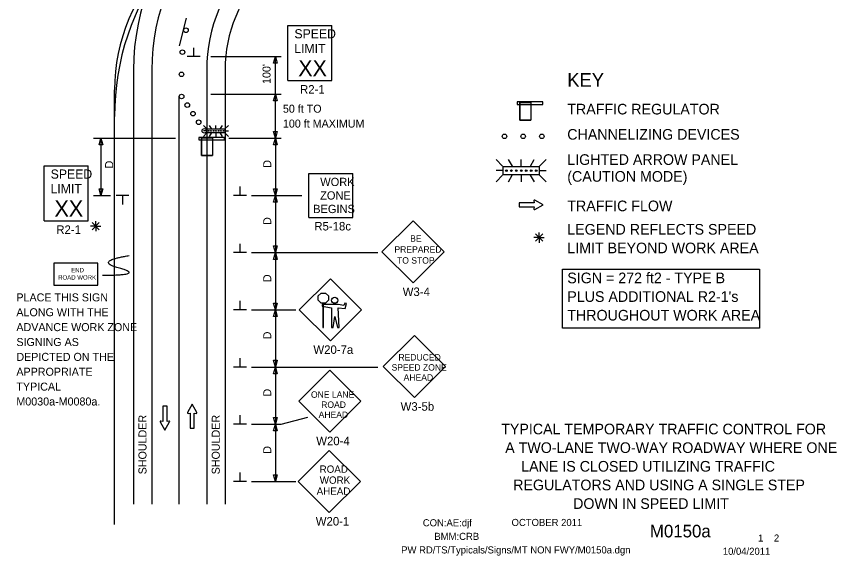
# Model space of a CAD drawing. Extents: x 16735 to 18481, y 5932 to 6923.
# Drawn here: x 16735 to 17452, y 5932 to 6404 of the extents above; entities that cross this region are included whole.
import ezdxf

# ---------------------------------------------------------------- set-up
doc = ezdxf.new("R2010")
doc.units = 0
for name, color, linetype in [('ALI_LEGAL_EX', 7, 'Continuous'), ('BORDER_SIGNAL_WO', 7, 'Continuous'), ('MT_SCRATCH_LEVEL_E', 7, 'Continuous'), ('PAVT_EDGE_EX', 7, 'Continuous'), ('TRAFFIC_SIGNS_PR', 7, 'Continuous'), ('TYPICAL_TEXT_DIMEN_EX', 7, 'Continuous'), ('TYPICAL_TEXT_DIMEN_PR', 7, 'Continuous')]:
    doc.layers.add(name, color=color, linetype=linetype)

msp = doc.modelspace()

# ---------------------------------------------------------------- linework, layer by layer
at = {"layer": 'ALI_LEGAL_EX'}
msp.add_line((16821.31, 5959.79), (16821.31, 6316.41), dxfattribs=at)
msp.add_arc((17042.09, 6317.17), 220.78, 142.68987, 180.19827, dxfattribs=at)
at = {"layer": 'MT_SCRATCH_LEVEL_E'}
for p, q in [((17188.17, 6240.97), (17174.91, 6240.97)), ((17174.91, 6240.97), (17174.91, 6237.23)), ((17188.17, 6240.97), (17174.91, 6240.97)), ((17174.91, 6240.97), (17174.91, 6237.23)), ((17174.91, 6237.23), (17188.17, 6237.23)), ((17174.91, 6237.23), (17188.17, 6237.23)), ((17187.85, 6242.75), (17188.17, 6240.97)), ((17187.85, 6242.75), (17188.17, 6240.97)), ((17188.17, 6237.23), (17187.85, 6235.45)), ((17188.17, 6237.23), (17187.85, 6235.45)), ((17195.78, 6239.12), (17188.54, 6243.23)), ((17195.78, 6239.12), (17188.54, 6243.23)), ((17188.54, 6234.97), (17195.78, 6239.12)), ((17188.54, 6234.97), (17195.78, 6239.12)), ((16867.14, 6063.03), (16863.4, 6063.03)), ((16863.4, 6063.03), (16863.4, 6049.78)), ((16867.14, 6063.03), (16863.4, 6063.03)), ((16863.4, 6063.03), (16863.4, 6049.78)), ((16867.14, 6049.78), (16867.14, 6063.03)), ((16867.14, 6049.78), (16867.14, 6063.03)), ((16889.11, 6064.72), (16885, 6057.48)), ((16889.11, 6064.72), (16885, 6057.48)), ((16893.26, 6057.48), (16889.11, 6064.72)), ((16893.26, 6057.48), (16889.11, 6064.72)), ((16885.48, 6056.8), (16887.26, 6057.11)), ((16885.48, 6056.8), (16887.26, 6057.11)), ((16887.26, 6057.11), (16887.26, 6043.86)), ((16887.26, 6057.11), (16887.26, 6043.86)), ((16891, 6043.86), (16891, 6057.11)), ((16891, 6057.11), (16892.78, 6056.8)), ((16891, 6043.86), (16891, 6057.11)), ((16891, 6057.11), (16892.78, 6056.8)), ((16861.15, 6049.41), (16865.29, 6042.17)), ((16861.15, 6049.41), (16865.29, 6042.17)), ((16863.4, 6049.78), (16861.62, 6050.09)), ((16863.4, 6049.78), (16861.62, 6050.09)), ((16865.29, 6042.17), (16869.4, 6049.41)), ((16865.29, 6042.17), (16869.4, 6049.41)), ((16868.92, 6050.09), (16867.14, 6049.78)), ((16868.92, 6050.09), (16867.14, 6049.78)), ((16887.26, 6043.86), (16891, 6043.86)), ((16887.26, 6043.86), (16891, 6043.86))]:
    msp.add_line(p, q, dxfattribs=at)
for centre, start, end in [((17188.31, 6242.82), 60.42484, 189.96381), ((17188.31, 6242.82), 60.42484, 189.96381), ((17188.31, 6235.38), 170.03619, 299.77312), ((17188.31, 6235.38), 170.03619, 299.77312), ((16885.41, 6057.26), 150.42484, 279.96381), ((16885.41, 6057.26), 150.42484, 279.96381), ((16892.85, 6057.26), 260.03619, 29.77312), ((16892.85, 6057.26), 260.03619, 29.77312), ((16861.55, 6049.63), 80.03619, 209.77312), ((16861.55, 6049.63), 80.03619, 209.77312), ((16869, 6049.63), 330.42484, 99.96381), ((16869, 6049.63), 330.42484, 99.96381)]:
    msp.add_arc(centre, 0.463, start, end, dxfattribs=at)
at = {"layer": 'PAVT_EDGE_EX'}
for p, q in [((16837.83, 6357.23), (16837.83, 5977.53)), ((16853.83, 6357.23), (16853.83, 5977.53)), ((16901.83, 6357.23), (16901.83, 5977.53)), ((16917.83, 6357.23), (16917.83, 5977.53)), ((16821.31, 5959.79), (16821.31, 6339.5)), ((16877.83, 5977.53), (16877.83, 6334.14))]:
    msp.add_line(p, q, dxfattribs=at)
for points in [[(16878.08, 6378.11), (16884.28, 6402.33)], [(16877.83, 6277.53), (16877.83, 6302.53)], [(16877.83, 6277.53), (16877.83, 6302.53)], [(16877.83, 6177.53), (16877.83, 6202.53)], [(16877.83, 6177.53), (16877.83, 6202.53)], [(16877.83, 6077.53), (16877.83, 6102.53)], [(16877.83, 6077.53), (16877.83, 6102.53)], [(16877.83, 5977.53), (16877.83, 6002.53)], [(16877.83, 5977.53), (16877.83, 6002.53)]]:
    msp.add_lwpolyline(points, dxfattribs=at)
for centre, radius, start, end in [((17037.83, 6357.23), 200, 134.42576, 179.99991), ((17037.83, 6357.23), 184, 134.42582, 180.00009), ((16981.31, 6339.5), 160, 134.35623, 180.00012), ((17037.83, 6357.23), 136, 134.35623, 180.00013), ((17037.83, 6357.23), 120, 134.35623, 180.00014)]:
    msp.add_arc(centre, radius, start, end, dxfattribs=at)
at = {"layer": 'TRAFFIC_SIGNS_PR'}
for p, q in [((16972.73, 6395.76), (17011.13, 6395.76)), ((16972.73, 6347.76), (16972.73, 6395.76)), ((17011.13, 6347.76), (17011.13, 6395.76)), ((16972.73, 6347.76), (17011.13, 6347.76)), ((17175.6, 6328.65), (17175.6, 6313.05)), ((17185.19, 6328.65), (17185.19, 6313.05)), ((17175.6, 6313.05), (17185.19, 6313.05)), ((16898.92, 6308.57), (16901.74, 6305.75)), ((16901.74, 6303.72), (16898.92, 6303.72)), ((16898.92, 6298.87), (16901.74, 6301.69)), ((16903.38, 6303.72), (16903.38, 6303.72)), ((16904.36, 6298.86), (16905.99, 6301.69)), ((16906.01, 6305.75), (16904.39, 6308.57)), ((16905.56, 6303.72), (16905.56, 6303.72)), ((16907.73, 6303.72), (16907.73, 6303.72)), ((16909.83, 6305.75), (16909.83, 6308.57)), ((16909.83, 6301.69), (16909.83, 6298.86)), ((16909.9, 6303.72), (16909.9, 6303.72)), ((16912.08, 6303.72), (16912.08, 6303.72)), ((16913.96, 6305.75), (16915.59, 6308.57)), ((16915.62, 6298.86), (16913.99, 6301.69)), ((16914.25, 6303.72), (16914.25, 6303.72)), ((16916.42, 6303.72), (16916.42, 6303.72)), ((16917.91, 6305.75), (16920.74, 6308.57)), ((16917.91, 6303.72), (16920.74, 6303.72)), ((16917.91, 6301.69), (16920.74, 6298.86)), ((16897.31, 6297.69), (16897.31, 6282.08)), ((16906.89, 6297.69), (16906.89, 6282.08)), ((16897.31, 6282.08), (16906.89, 6282.08)), ((16759.69, 6273.11), (16798.09, 6273.11)), ((16759.69, 6225.11), (16759.69, 6273.11)), ((16798.09, 6225.11), (16798.09, 6273.11)), ((17154.83, 6278.65), (17160.47, 6273.01)), ((17169.01, 6273.01), (17165.75, 6278.65)), ((17176.64, 6273.01), (17176.64, 6278.65)), ((17184.91, 6273.01), (17188.16, 6278.65)), ((17192.81, 6273.01), (17198.45, 6278.65)), ((16991.07, 6228.14), (16991.07, 6266.53)), ((16991.07, 6266.53), (17029.47, 6266.53)), ((17029.47, 6228.14), (17029.47, 6266.53)), ((17160.47, 6268.95), (17154.83, 6268.95)), ((17163.74, 6268.95), (17163.74, 6268.95)), ((17168.09, 6268.95), (17168.09, 6268.95)), ((17172.44, 6268.95), (17172.44, 6268.95)), ((17176.79, 6268.95), (17176.79, 6268.95)), ((17181.13, 6268.95), (17181.13, 6268.95)), ((17185.48, 6268.95), (17185.48, 6268.95)), ((17189.83, 6268.95), (17189.83, 6268.95)), ((17192.81, 6268.95), (17198.45, 6268.95)), ((17154.83, 6259.25), (17160.47, 6264.88)), ((17165.7, 6259.24), (17168.95, 6264.88)), ((17176.64, 6264.88), (17176.64, 6259.24)), ((17188.21, 6259.24), (17184.96, 6264.88)), ((17192.81, 6264.88), (17198.45, 6259.24)), ((16759.69, 6225.11), (16798.09, 6225.11)), ((16991.07, 6228.14), (17029.47, 6228.14)), ((17082.14, 6225.12), (17054.99, 6197.96)), ((17109.3, 6197.96), (17082.14, 6225.12)), ((17054.99, 6197.96), (17082.14, 6170.81)), ((17082.14, 6170.81), (17109.3, 6197.96)), ((17009.93, 6174.53), (16982.78, 6147.38)), ((17037.08, 6147.38), (17009.93, 6174.53)), ((16982.78, 6147.38), (17009.93, 6120.22)), ((17009.93, 6120.22), (17037.08, 6147.38)), ((17083.33, 6124.84), (17056.18, 6097.68)), ((17110.49, 6097.68), (17083.33, 6124.84)), ((17009.37, 6094.69), (16982.22, 6067.54)), ((17036.52, 6067.54), (17009.37, 6094.69)), ((17056.18, 6097.68), (17083.33, 6070.53)), ((17083.33, 6070.53), (17110.49, 6097.68)), ((16982.22, 6067.54), (17009.37, 6040.39)), ((17009.37, 6040.39), (17036.52, 6067.54)), ((17008.97, 6024.47), (16981.82, 5997.32)), ((17036.12, 5997.32), (17008.97, 6024.47)), ((16981.82, 5997.32), (17008.97, 5970.17)), ((17008.97, 5970.17), (17036.12, 5997.32))]:
    msp.add_line(p, q, dxfattribs=at)
for points in [[(17195.6, 6328.98), (17173.22, 6328.98), (17173.22, 6326.88), (17195.6, 6326.88)], [(17175.6, 6328.65), (17185.19, 6328.65), (17185.19, 6313.05), (17175.6, 6313.05)], [(16917.68, 6301.92), (16901.98, 6301.92), (16901.98, 6305.52), (16917.68, 6305.52)], [(16917.3, 6298.02), (16894.92, 6298.02), (16894.92, 6295.92), (16917.3, 6295.92)], [(16897.31, 6297.69), (16906.89, 6297.69), (16906.89, 6282.08), (16897.31, 6282.08)], [(17192.35, 6265.35), (17160.93, 6265.35), (17160.93, 6272.55), (17192.35, 6272.55)], [(16768.35, 6168.96), (16806.75, 6168.96), (16806.75, 6188.16), (16768.35, 6188.16)], [(17001.89, 6162.01), (17005.57, 6162.01), (17008.17, 6159.41), (17008.17, 6155.74), (17005.57, 6153.14), (17001.89, 6153.14), (16999.3, 6155.74), (16999.3, 6159.41)], [(17016.61, 6152.1), (17002.79, 6152.1), (17002.79, 6150.6), (17010.76, 6149.14), (17010.76, 6131.74), (17012.26, 6131.74), (17013.76, 6141.34), (17016.16, 6131.74), (17017.66, 6131.74), (17016.76, 6149.14), (17022.76, 6148.54), (17023.96, 6152.74), (17022.5, 6153.11), (17021.6, 6151.01)], [(17003.43, 6153.14), (17003.43, 6131.76), (17004.03, 6131.76), (17004.03, 6153.14)]]:
    msp.add_lwpolyline(points, close=True, dxfattribs=at)
for centre, radius in [((16883.63, 6391.67), 2), ((16880.58, 6372.54), 2), ((16879.83, 6353.18), 2), ((16879.87, 6333.79), 2), ((16884.84, 6326.28), 2), ((16889.81, 6318.78), 2), ((16894.78, 6311.27), 2), ((16899.75, 6303.77), 2), ((16903.4, 6303.72), 0.379), ((16905.55, 6303.72), 0.379), ((16907.73, 6303.72), 0.379), ((16909.9, 6303.72), 0.379), ((16912.08, 6303.72), 0.379), ((16914.25, 6303.72), 0.379), ((16916.42, 6303.72), 0.379), ((17162.15, 6298.98), 2), ((17178.45, 6298.98), 2), ((17194.75, 6298.98), 2), ((17163.78, 6268.95), 0.758), ((17168.09, 6268.95), 0.758), ((17172.44, 6268.95), 0.758), ((17176.79, 6268.95), 0.758), ((17181.13, 6268.95), 0.758), ((17185.48, 6268.95), 0.758), ((17189.83, 6268.95), 0.758), ((17013.74, 6155.71), 2.7)]:
    msp.add_circle(centre, radius, dxfattribs=at)
msp.add_open_spline([(16810.87, 6177.57), (16848.26, 6177.57), (16802.77, 6189.69), (16833.92, 6194.74)], degree=2, dxfattribs=at)
at = {"layer": 'TYPICAL_TEXT_DIMEN_EX'}
msp.add_lwpolyline([(17212.8, 6182.98), (17385.09, 6182.98), (17385.09, 6131.22), (17212.8, 6131.22)], close=True, dxfattribs=at)
at = {"layer": 'TYPICAL_TEXT_DIMEN_PR'}
for p, q in [((16890.51, 6368.68), (16890.51, 6376.46)), ((16896.13, 6368.68), (16884.88, 6368.68)), ((16905.56, 6368.68), (16966.83, 6368.68)), ((16960.26, 6362.81), (16961.83, 6368.68)), ((16960.26, 6362.81), (16961.83, 6368.68)), ((16961.83, 6368.68), (16963.4, 6362.81)), ((16961.83, 6368.68), (16963.4, 6362.81)), ((16961.83, 6335.81), (16961.83, 6368.68)), ((16961.83, 6362.81), (16960.26, 6362.81)), ((16961.83, 6362.81), (16960.26, 6362.81)), ((16963.4, 6362.81), (16961.83, 6362.81)), ((16963.4, 6362.81), (16961.83, 6362.81)), ((16905.56, 6335.81), (16966.83, 6335.81)), ((16960.26, 6329.94), (16961.83, 6335.81)), ((16960.26, 6329.94), (16961.83, 6335.81)), ((16961.83, 6297.3), (16961.83, 6335.81)), ((16961.83, 6335.81), (16963.4, 6329.94)), ((16961.83, 6335.81), (16963.4, 6329.94)), ((16961.83, 6329.94), (16960.26, 6329.94)), ((16961.83, 6329.94), (16960.26, 6329.94)), ((16963.4, 6329.94), (16961.83, 6329.94)), ((16963.4, 6329.94), (16961.83, 6329.94)), ((16961.83, 6297.3), (16960.26, 6303.16)), ((16960.26, 6303.16), (16961.83, 6303.16)), ((16961.83, 6297.3), (16960.26, 6303.16)), ((16960.26, 6303.16), (16961.83, 6303.16)), ((16961.83, 6303.16), (16963.4, 6303.16)), ((16963.4, 6303.16), (16961.83, 6297.3)), ((16961.83, 6303.16), (16963.4, 6303.16)), ((16963.4, 6303.16), (16961.83, 6297.3)), ((16802.83, 6297.3), (16874.44, 6297.3)), ((16807.86, 6291.44), (16809.43, 6297.3)), ((16809.43, 6297.3), (16809.43, 6247.3)), ((16809.43, 6297.3), (16811, 6291.44)), ((16921.12, 6297.3), (16966.83, 6297.3)), ((16960.26, 6291.44), (16961.83, 6297.3)), ((16960.26, 6291.44), (16961.83, 6297.3)), ((16961.83, 6297.3), (16961.83, 6247.3)), ((16961.83, 6297.3), (16963.4, 6291.44)), ((16961.83, 6297.3), (16963.4, 6291.44)), ((16809.43, 6291.44), (16807.86, 6291.44)), ((16811, 6291.44), (16809.43, 6291.44)), ((16961.83, 6291.44), (16960.26, 6291.44)), ((16961.83, 6291.44), (16960.26, 6291.44)), ((16963.4, 6291.44), (16961.83, 6291.44)), ((16963.4, 6291.44), (16961.83, 6291.44)), ((16809.43, 6247.3), (16807.86, 6253.16)), ((16807.86, 6253.16), (16809.43, 6253.16)), ((16809.43, 6253.16), (16811, 6253.16)), ((16811, 6253.16), (16809.43, 6247.3)), ((16930.95, 6247.3), (16930.95, 6255.09)), ((16961.83, 6247.3), (16960.26, 6253.16)), ((16960.26, 6253.16), (16961.83, 6253.16)), ((16961.83, 6247.3), (16960.26, 6253.16)), ((16960.26, 6253.16), (16961.83, 6253.16)), ((16961.83, 6253.16), (16963.4, 6253.16)), ((16963.4, 6253.16), (16961.83, 6247.3)), ((16961.83, 6253.16), (16963.4, 6253.16)), ((16963.4, 6253.16), (16961.83, 6247.3)), ((16802.83, 6247.3), (16817.69, 6247.3)), ((16833.83, 6247.3), (16822.58, 6247.3)), ((16828.21, 6247.3), (16828.21, 6239.52)), ((16936.58, 6247.3), (16925.33, 6247.3)), ((16940.83, 6247.3), (16984.99, 6247.3)), ((16960.26, 6241.44), (16961.83, 6247.3)), ((16960.26, 6241.44), (16961.83, 6247.3)), ((16961.83, 6247.3), (16963.4, 6241.44)), ((16961.83, 6247.3), (16963.4, 6241.44)), ((16961.83, 6247.3), (16961.83, 6197.3)), ((16961.83, 6241.44), (16960.26, 6241.44)), ((16961.83, 6241.44), (16960.26, 6241.44)), ((16963.4, 6241.44), (16961.83, 6241.44)), ((16963.4, 6241.44), (16961.83, 6241.44)), ((16801.59, 6223.64), (16807.97, 6217.26)), ((16807.97, 6223.64), (16801.59, 6217.26)), ((16804.78, 6220.45), (16804.78, 6224.9)), ((16804.78, 6220.45), (16800.25, 6220.45)), ((16804.78, 6220.45), (16807.97, 6220.45)), ((16804.78, 6220.45), (16809.26, 6220.45)), ((16804.78, 6220.45), (16804.78, 6215.95)), ((17192.4, 6210.48), (17187.86, 6210.48)), ((17189.21, 6213.67), (17195.58, 6207.29)), ((17195.58, 6213.67), (17189.21, 6207.29)), ((17192.4, 6210.48), (17192.4, 6214.94)), ((17192.4, 6210.48), (17195.58, 6210.48)), ((17192.4, 6210.48), (17196.87, 6210.48)), ((17192.4, 6210.48), (17192.4, 6205.98)), ((16930.95, 6197.3), (16930.95, 6205.09)), ((16961.83, 6197.3), (16960.26, 6203.16)), ((16960.26, 6203.16), (16961.83, 6203.16)), ((16961.83, 6197.3), (16960.26, 6203.16)), ((16960.26, 6203.16), (16961.83, 6203.16)), ((16961.83, 6203.16), (16963.4, 6203.16)), ((16963.4, 6203.16), (16961.83, 6197.3)), ((16961.83, 6203.16), (16963.4, 6203.16)), ((16963.4, 6203.16), (16961.83, 6197.3)), ((16936.58, 6197.3), (16925.33, 6197.3)), ((16940.83, 6197.3), (17051.33, 6197.3)), ((16960.26, 6191.44), (16961.83, 6197.3)), ((16960.26, 6191.44), (16961.83, 6197.3)), ((16961.83, 6197.3), (16961.83, 6147.3)), ((16961.83, 6197.3), (16963.4, 6191.44)), ((16961.83, 6197.3), (16963.4, 6191.44)), ((16961.83, 6191.44), (16960.26, 6191.44)), ((16961.83, 6191.44), (16960.26, 6191.44)), ((16963.4, 6191.44), (16961.83, 6191.44)), ((16963.4, 6191.44), (16961.83, 6191.44)), ((16930.95, 6147.3), (16930.95, 6155.09)), ((16961.83, 6147.3), (16960.26, 6153.16)), ((16960.26, 6153.16), (16961.83, 6153.16)), ((16961.83, 6147.3), (16960.26, 6153.16)), ((16960.26, 6153.16), (16961.83, 6153.16)), ((16961.83, 6153.16), (16963.4, 6153.16)), ((16963.4, 6153.16), (16961.83, 6147.3)), ((16961.83, 6153.16), (16963.4, 6153.16)), ((16963.4, 6153.16), (16961.83, 6147.3)), ((16936.58, 6147.3), (16925.33, 6147.3)), ((16940.83, 6147.3), (16979.83, 6147.3)), ((16960.26, 6141.44), (16961.83, 6147.3)), ((16960.26, 6141.44), (16961.83, 6147.3)), ((16961.83, 6147.3), (16961.83, 6097.3)), ((16961.83, 6147.3), (16963.4, 6141.44)), ((16961.83, 6147.3), (16963.4, 6141.44)), ((16961.83, 6141.44), (16960.26, 6141.44)), ((16961.83, 6141.44), (16960.26, 6141.44)), ((16963.4, 6141.44), (16961.83, 6141.44)), ((16963.4, 6141.44), (16961.83, 6141.44)), ((16930.95, 6097.3), (16930.95, 6105.09)), ((16961.83, 6097.3), (16960.26, 6103.16)), ((16960.26, 6103.16), (16961.83, 6103.16)), ((16961.83, 6097.3), (16960.26, 6103.16)), ((16960.26, 6103.16), (16961.83, 6103.16)), ((16961.83, 6103.16), (16963.4, 6103.16)), ((16963.4, 6103.16), (16961.83, 6097.3)), ((16961.83, 6103.16), (16963.4, 6103.16)), ((16963.4, 6103.16), (16961.83, 6097.3)), ((16936.58, 6097.3), (16925.33, 6097.3)), ((16940.83, 6097.3), (17051.33, 6097.3)), ((16960.26, 6091.44), (16961.83, 6097.3)), ((16960.26, 6091.44), (16961.83, 6097.3)), ((16961.83, 6097.3), (16961.83, 6047.3)), ((16961.83, 6097.3), (16963.4, 6091.44)), ((16961.83, 6097.3), (16963.4, 6091.44)), ((16961.83, 6091.44), (16960.26, 6091.44)), ((16961.83, 6091.44), (16960.26, 6091.44)), ((16963.4, 6091.44), (16961.83, 6091.44)), ((16963.4, 6091.44), (16961.83, 6091.44)), ((16930.95, 6047.3), (16930.95, 6055.09)), ((16961.83, 6047.3), (16960.26, 6053.16)), ((16960.26, 6053.16), (16961.83, 6053.16)), ((16961.83, 6047.3), (16960.26, 6053.16)), ((16960.26, 6053.16), (16961.83, 6053.16)), ((16961.83, 6053.16), (16963.4, 6053.16)), ((16963.4, 6053.16), (16961.83, 6047.3)), ((16961.83, 6053.16), (16963.4, 6053.16)), ((16963.4, 6053.16), (16961.83, 6047.3)), ((16966.83, 6047.3), (16990.07, 6053.54)), ((16936.58, 6047.3), (16925.33, 6047.3)), ((16940.83, 6047.3), (16966.83, 6047.3)), ((16960.26, 6041.44), (16961.83, 6047.3)), ((16960.26, 6041.44), (16961.83, 6047.3)), ((16961.83, 6047.3), (16961.83, 5997.3)), ((16961.83, 6047.3), (16963.4, 6041.44)), ((16961.83, 6047.3), (16963.4, 6041.44)), ((16961.83, 6041.44), (16960.26, 6041.44)), ((16961.83, 6041.44), (16960.26, 6041.44)), ((16963.4, 6041.44), (16961.83, 6041.44)), ((16963.4, 6041.44), (16961.83, 6041.44)), ((16930.95, 5997.3), (16930.95, 6005.09)), ((16961.83, 5997.3), (16960.26, 6003.16)), ((16960.26, 6003.16), (16961.83, 6003.16)), ((16961.83, 6003.16), (16963.4, 6003.16)), ((16963.4, 6003.16), (16961.83, 5997.3)), ((16936.58, 5997.3), (16925.33, 5997.3)), ((16940.83, 5997.3), (16979.58, 5997.3))]:
    msp.add_line(p, q, dxfattribs=at)

# ---------------------------------------------------------------- texts
at = {"layer": 'BORDER_SIGNAL_WO'}
for s, height, p in [('TYPICAL TEMPORARY TRAFFIC CONTROL FOR', 9.3, (17159.21, 6038.47)), ('A TWO-LANE TWO-WAY ROADWAY WHERE ONE', 9.3, (17162.73, 6022.17)), ('LANE IS CLOSED UTILIZING TRAFFIC', 9.3, (17176.71, 6005.87)), ('REGULATORS AND USING A SINGLE STEP', 9.3, (17169.71, 5989.57)), ('DOWN IN SPEED LIMIT', 9.3, (17222.08, 5973.27)), ('CON:AE:djf', 6.2, (17090.69, 5958.06)), ('    OCTOBER 2011    ', 6.2, (17159.08, 5958.34)), ('    M0150a   ', 11, (17272.86, 5948.38)), ('BMM:CRB   ', 6.2, (17100.81, 5946.17)), (' 1    2 ', 6.2, (17381.45, 5944.7)), ('PW RD/TS/Typicals/Signs/MT NON FWY/M0150a.dgn    ', 6.2, (17071.79, 5934.33)), ('10/04/2011    ', 6.2, (17352.93, 5933.13))]:
    msp.add_text(s, height=height, dxfattribs=at).set_placement(p)
at = {"layer": 'TRAFFIC_SIGNS_PR'}
for s, height, p in [('SPEED', 8, (16978.5, 6384.62)), ('LIMIT', 8, (16978.34, 6371.82)), ('XX', 14.031, (16981.85, 6351.51)), ('R2-1', 7.44, (16983.41, 6336.32)), ('SPEED', 8, (16765.46, 6261.97)), ('WORK', 7.217, (17001.06, 6255.5)), ('LIMIT', 8, (16765.3, 6249.17)), ('ZONE', 7.217, (17000.95, 6243.69)), ('XX', 14.031, (16768.8, 6228.87)), ('BEGINS', 7.217, (16994.87, 6231.88)), ('R5-18c', 7.44, (16995.88, 6216.69)), ('R2-1', 7.44, (16770.37, 6213.67)), ('BE', 5.6, (17079.64, 6206.89)), ('PREPARED', 5.6, (17065.89, 6197.29)), ('TO STOP', 5.6, (17068.17, 6187.69)), ('END', 3.831, (16783.35, 6180.09)), ('ROAD WORK', 3.831, (16771.96, 6173.7)), ('W3-4', 7.44, (17073.15, 6159.37)), ('W20-7a', 7.44, (16995.07, 6108.78)), ('REDUCED', 5.6, (17069.39, 6102.99)), ('SPEED ZONE', 5.6, (17063.38, 6094.19)), ('AHEAD', 5.6, (17073.94, 6085.39)), ('ONE LANE', 5.6, (16992.95, 6070.41)), ('ROAD', 5.6, (17001.9, 6061.61)), ('W3-5b', 7.44, (17071.29, 6059.09)), ('AHEAD', 5.6, (16999.66, 6052.81)), ('W20-4', 7.44, (16997.55, 6028.95)), ('ROAD', 6.4, (17000.51, 6004.85)), ('WORK', 6.4, (17000.62, 5995.25)), ('AHEAD', 6.4, (16997.93, 5985.65)), ('W20-1', 7.44, (16997.14, 5958.73))]:
    msp.add_text(s, height=height, dxfattribs=at).set_placement(p)
for s, p in [('PLACE THIS SIGN ', (16735.47, 6154.68)), ('ALONG WITH THE', (16735.47, 6141.68)), ('ADVANCE WORK ZONE ', (16735.47, 6128.68)), ('SIGNING AS', (16735.47, 6115.68)), ('DEPICTED ON THE ', (16735.47, 6102.68)), ('APPROPRIATE', (16735.47, 6089.68)), ('TYPICAL ', (16735.47, 6076.68)), ('M0030a-M0080a.', (16735.47, 6063.68))]:
    msp.add_text(s, height=7, rotation=360, dxfattribs=at).set_placement(p)
at = {"layer": 'TYPICAL_TEXT_DIMEN_EX'}
for s, height, p in [('KEY', 12, (17216.99, 6342.3)), ('TRAFFIC REGULATOR', 9.3, (17216.99, 6318.09)), ('CHANNELIZING DEVICES', 9.3, (17216.99, 6296.04)), ('LIGHTED ARROW PANEL', 9.3, (17216.99, 6273.99)), ('(CAUTION MODE)', 9.3, (17216.99, 6259.29)), ('TRAFFIC FLOW', 9.3, (17216.99, 6233.49)), ('LEGEND REFLECTS SPEED', 9.3, (17216.99, 6213.04)), ('LIMIT BEYOND WORK AREA', 9.3, (17216.99, 6196.74)), ('SIGN = 272 ft2 - TYPE B', 9.3, (17216.99, 6170.54)), ("PLUS ADDITIONAL R2-1's", 9.3, (17216.99, 6154.24)), ('THROUGHOUT WORK AREA', 9.3, (17216.99, 6137.94))]:
    msp.add_text(s, height=height, dxfattribs=at).set_placement(p)
at = {"layer": 'TYPICAL_TEXT_DIMEN_PR'}
for s, p in [("100'", (16957.64, 6344.74)), ('D', (16820.03, 6270.95)), ('D', (16958.24, 6271.52)), ('D', (16958.24, 6221.52)), ('D', (16958.24, 6171.52)), ('D', (16958.24, 6121.52)), ('D', (16958.24, 6071.52)), ('SHOULDER', (16849.18, 6003.49)), ('SHOULDER', (16913.23, 6003.49)), ('D', (16958.24, 6021.52))]:
    msp.add_text(s, height=7, rotation=90, dxfattribs=at).set_placement(p)
for s, p in [('50 ft TO', (16968.42, 6319.61)), ('100 ft MAXIMUM', (16968.42, 6306.61))]:
    msp.add_text(s, height=7, dxfattribs=at).set_placement(p)

doc.saveas('drawing.dxf')
